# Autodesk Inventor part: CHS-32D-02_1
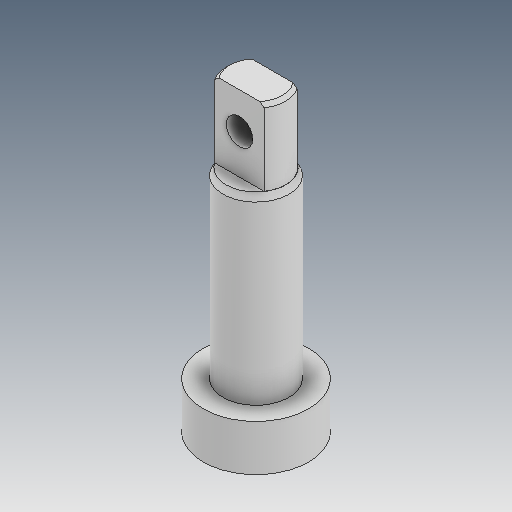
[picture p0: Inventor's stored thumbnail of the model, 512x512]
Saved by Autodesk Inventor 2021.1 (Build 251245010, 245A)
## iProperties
Created: 2021-05
Part Number: CHS-32D-02_1
Material: Ogólny
Document SubType Name: Modeling
Designer: user
Density: 1 g/cm^3
Appearance: Domyślna
Author: user
Revision Number: ÈÎºÎ
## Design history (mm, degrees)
feature "ÊäÈë1"
feature "ÊäÈë2"
node "Bryła1"
node "Bryła2"
